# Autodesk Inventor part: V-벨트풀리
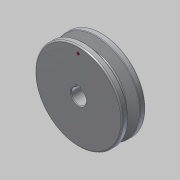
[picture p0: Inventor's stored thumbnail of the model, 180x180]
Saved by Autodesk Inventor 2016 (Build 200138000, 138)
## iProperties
Created: 2016-08
Part Number: V-벨트풀리
Material: 알루미늄 6061
Document SubType Name: Modeling
Designer: mduedu
Density: 2.71 g/cm^3
Appearance: 알루미늄 - 평지
Author: mduedu
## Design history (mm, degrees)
sketch "스케치1"
  geometry: L1 (0, 9.5)-(0, -9.5); L2 (0, 9.5)-(35, 9.5); L3 (35, 9.5)-(35, 4.825); L4 (35, 4.825)-(26, 2.074); L5 (26, 2.074)-(26, 0); L6 (0, 0)-(26, 0); L7 (0, -9.5)-(35, -9.5); L8 (35, -9.5)-(35, -4.825); L9 (35, -4.825)-(26, -2.074); L10 (26, -2.074)-(26, 0); L11 (32.3, 9.5)-(32.3, -9.5); 3 further points
  constraints: 22 end point, 6 point on line, 4 perpendicular, 3 symmetric about line, 1 coincident, 1 horizontal alignment, 1 midpoint, 1 parallel, 1 vertical
  dimensions: "d0" = 19 distance of L1.start L1.end; "d2" = 70 diameter of L8 L1; "d4" = 6.3 distance between parallel lines of L10 L11; "d5" = 2.7 distance between parallel lines of L11 L8; "d6" = 8 distance of point (32.3, -4) point (32.3, 4); "d7" = 34 deg angle of L9 L4
revolve "회전1" sketch "스케치1" stored, may be unused: angle "d8" = 90 deg
sketch "스케치2"
  geometry: L1 (-2, 0)-(2, 0); L2 (2, 0)-(2, 7.8); L3 (2, 7.8)-(-2, 7.8); L4 (-2, 7.8)-(-2, 0); C1 r 6 at (0, 0); 2 further points
  constraints: 8 end point, 2 coincident, 2 parallel, 1 centre point, 1 horizontal, 1 midpoint, 1 perpendicular
  dimensions: "d9" = 12 diameter of C1; "d11" = 4 distance of L2.end L3.end; "d12" = 7.8 distance of L1.end L2.end
extrude "돌출1" cut sketch "스케치2" stored distance "d13" = 10; taper "d14" = 0 deg
sketch "스케치4"
  geometry: C1 r 22 at (0, 0); C2 r 12 at (0, 0); 1 further point
  constraints: 2 centre point, 2 coincident
  dimensions: "d32" = 44 diameter of C1; "d34" = 24 diameter of C2
extrude "돌출2" cut sketch "스케치4" distance "d35" = 12; taper "d36" = 0 deg
fillet "모깎기1" dims "d20" = 0.5, "d21" = 1, "d37" = 1
fillet "모깎기6" dims "d38" = 3
chamfer "모따기1" distance "d26" = 0.5; stored, may be unused: second distance "d27" = 2, angle "d28" = 45 deg
sketch "스케치5" dims "d39" = 60
  geometry: C1 r 1 at (0, 30); 2 further points
  constraints: 2 vertical alignment, 1 centre point, 1 coincident, 2 other
  dimensions: "d40" = 2 diameter of C1
extrude "돌출3" join sketch "스케치5" distance "d41" = 0.5; taper "d42" = 0 deg
node "솔리드1"
